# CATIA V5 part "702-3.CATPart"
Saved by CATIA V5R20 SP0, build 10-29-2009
Part number: 702-3
Source: Unknown
Property "ARTICLENO": "702-3"
Property "BOMINFO": "702-3"
Property "CODE": "702-3"
Property "L": "90.000"
Property "LINA": "702-3"
Property "NB": "702-3"
Property "NBSYN": "$CODE."
Property "NN": "702"
Property "SUPPLIER": "CF"
Bounding box of the stored display mesh (mm): x -107 to 0, y 0 to 90, z -15 to 15
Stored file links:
  C:\Users\Utente\Desktop\3D files 702\702-3.CATPart
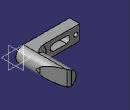
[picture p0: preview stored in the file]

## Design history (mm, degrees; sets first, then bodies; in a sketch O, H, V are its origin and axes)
Body1 "Geometry.1" (main body)
  Solid1 "702-3.catpart": solid without history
